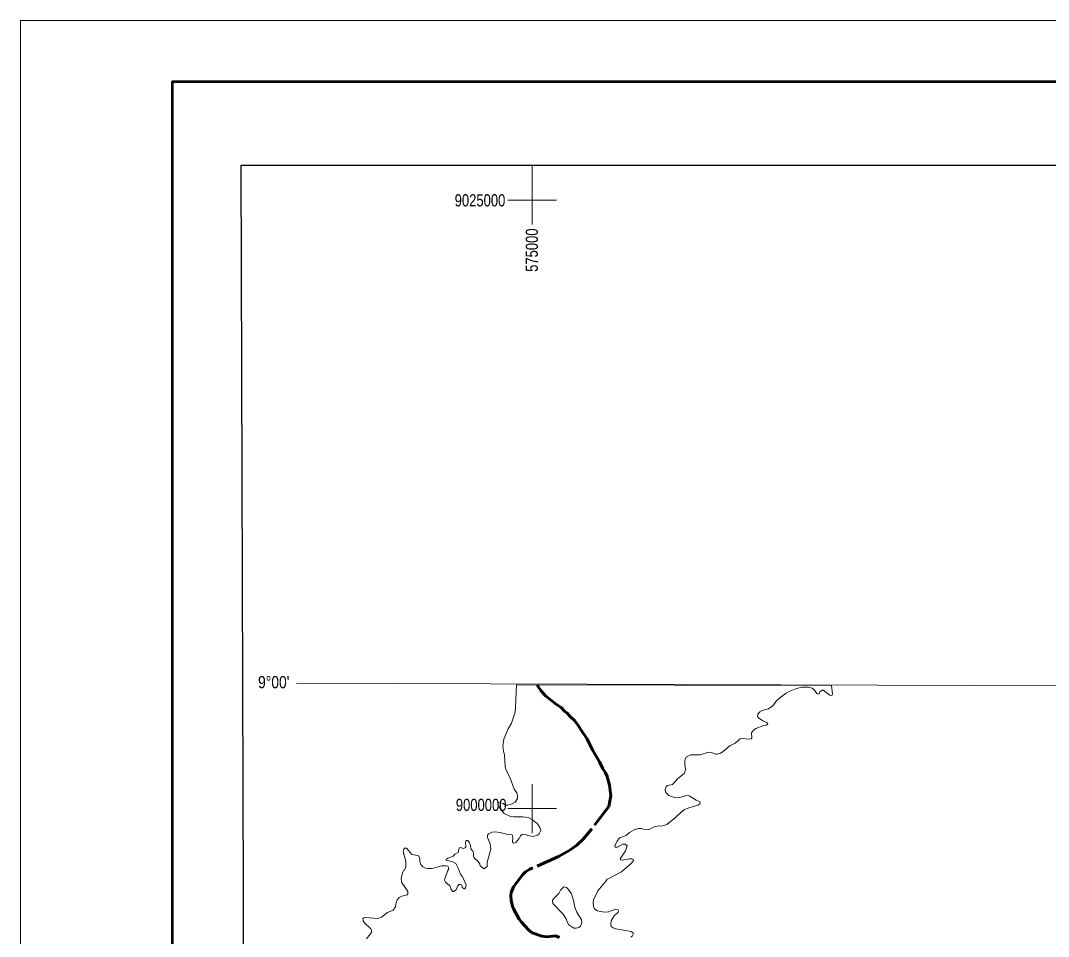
# Model space of a CAD drawing. Extents: x 553962 to 842807, y 8883888 to 9032388.
# Drawn here: x 553962 to 596222, y 8994735 to 9032388 of the extents above; entities that cross this region are included whole.
import ezdxf
from ezdxf.enums import TextEntityAlignment as Align

# ---------------------------------------------------------------- set-up
doc = ezdxf.new("R2010")
doc.units = 0
doc.header["$LTSCALE"] = 160
doc.linetypes.add('LONG_DASH_SHORT_DASH', pattern=[9.9, 6, -1.2, 1.5, -1.2])
for name, color, linetype, lineweight in [('1', 7, 'Continuous', 13), ('2', 7, 'Continuous', 13), ('21', 7, 'Continuous', 25), ('34', 7, 'LONG_DASH_SHORT_DASH', 60)]:
    doc.layers.add(name, color=color, linetype=linetype, lineweight=lineweight)

msp = doc.modelspace()

# ---------------------------------------------------------------- linework, layer by layer
at = {"layer": '1'}
for p, q in [((575000, 9024000), (575000, 9026438.8)), ((574000, 9025000), (576000, 9025000)), ((575000, 8999000), (575000, 9001000)), ((574000, 9000000), (576000, 9000000))]:
    msp.add_line(p, q, dxfattribs=at)
msp.add_lwpolyline([(842807.3, 9032387.8), (842807.3, 8883887.8), (553961.7, 8883887.8), (553961.7, 9032387.8)], close=True, dxfattribs=at)
at = {"layer": '1', "lineweight": 53}
msp.add_lwpolyline([(840307.3, 9029887.8), (840307.3, 8886387.8), (560211.7, 8886387.8), (560211.7, 9029887.8)], close=True, dxfattribs=at)
at = {"layer": '1', "lineweight": 25}
msp.add_lwpolyline([(563033.9, 9026438.8), (793061.1, 9026438.8), (793495.6, 8889836.8), (563468.3, 8889836.8)], close=True, dxfattribs=at)
at = {"layer": '2'}
msp.add_lwpolyline([(565303.2, 9005146.6), (664889.8, 9004806.7), (719872.1, 9004543.9), (791662, 9004102.7)], dxfattribs=at)
at = {"layer": '21', "lineweight": 13}
msp.add_line((587296.7, 9005052), (574348.1, 9005079.3), dxfattribs=at)
for points in [[(574348.1, 9005079.3), (574317.4, 9004163), (574295.7, 9003956), (574144.4, 9003506.6), (574014.7, 9003264.2), (573829.1, 9002845.8), (573792.1, 9002568.4), (573811.5, 9002356.8), (573854.8, 9002205), (573887.2, 9001708), (573923.9, 9001569.9), (574075.2, 9001284.5), (574252.7, 9000793.7), (574360.6, 9000635.8), (574399.5, 9000497.4), (574399.6, 9000400.4), (574293.6, 9000261.8), (574170.4, 9000188.3), (573989.5, 9000125.8), (573897.6, 9000125.8), (573807.4, 9000194.6), (573651.6, 9000255.2), (573610.4, 9000246.4), (573582.4, 9000173.4), (573662.4, 8999991.6), (573850.3, 8999788.5), (574105.5, 8999671.6), (574225.9, 8999652.2), (574616, 8999647.8), (574834.5, 8999622.2), (575013.7, 8999535.3), (575214.5, 8999368.9), (575311.9, 8999208.8), (575350.7, 8999090.1), (575283.8, 8998949.8), (575211.7, 8998895.2), (575030.5, 8998839.4), (574820.5, 8998888.6), (574709.3, 8998932.6), (574600.8, 8998934.5), (574550.9, 8998912.8), (574512, 8998871.7), (574467, 8998760.2), (574328, 8998599.3), (574233.6, 8998567), (574187.8, 8998629.6), (574204.6, 8998800.2), (574169.9, 8998917.3), (573924.2, 8998943.1), (573861.2, 8998973.3), (573495.9, 8999038.2), (573357.6, 8999025.2), (573195.7, 8998954), (573160.9, 8998904.1), (573154.4, 8998796.3), (573264.6, 8998547.5), (573290.5, 8998318.6), (573147.9, 8997786.5), (573147.7, 8997610.4), (573041.5, 8997523.5), (573000.7, 8997531.6), (572856.3, 8997643.8), (572845.2, 8997713), (572780.5, 8997814.4), (572609.7, 8997966), (572588, 8998037.6), (572585.8, 8998184.3), (572553.4, 8998244.8), (572469.1, 8998340), (572464.8, 8998478.1), (572423.8, 8998581.8), (572354.7, 8998677), (572291.7, 8998674.9), (572271.2, 8998655.2), (572257.2, 8998599.6), (572268, 8998409.4), (572236.1, 8998375.1), (572164.3, 8998348.7), (572065.1, 8998398.3), (572002.4, 8998374.6), (571967.6, 8998284), (571974, 8998195.7), (571816.4, 8998119.6), (571747.1, 8998035.2), (571528.9, 8997959.6), (571454.6, 8997898.7), (571466.8, 8997864.9), (571737.3, 8997804.6), (571855.7, 8997734.5), (571967.5, 8997514.1), (572052.2, 8997299.3), (572136.7, 8997188.2), (572285.2, 8996857.2), (572259.3, 8996727.3), (572229.1, 8996686.3), (572195.3, 8996686.2), (572121.1, 8996746.8), (572103.5, 8996844.1), (572051.6, 8996874.3), (571987.6, 8996870.2), (571987.6, 8996870.2)], [(578829.1, 8998253.7), (578829.1, 8998253.7), (578893.5, 8998421.2), (578896, 8998462.9), (578820.3, 8998527.9), (578723.1, 8998528), (578498.5, 8998400.6), (578409.9, 8998402.6), (578394.5, 8998476.1), (578489.6, 8998655.6), (578593.2, 8998782.9), (578859, 8998891.1), (578995.7, 8999003.7), (579185.5, 8999124.5), (579245.2, 8999145.9), (579291.8, 8999144.2), (579351.3, 8999169.6), (579492.4, 8999170), (579561.6, 8999144.2), (579767.2, 8999116.1), (580013.9, 8999239.3), (580201.7, 8999282.4), (580318.7, 8999271.8), (580526.2, 8999343.3), (580889.2, 8999621.9), (581105.3, 8999831.3), (581265.1, 8999950.3), (581472.9, 9000039.1), (581818.5, 9000129.8), (581887.7, 9000186), (581907.3, 9000221.2), (581887.7, 9000272.6), (581740.7, 9000331.1), (581525, 9000480), (581446.9, 9000516.8), (581343.2, 9000525.5), (581066.4, 9000443.4), (580893.5, 9000437), (580608.7, 9000531.7), (580484.7, 9000649.6), (580463.4, 9000778.4), (580500.2, 9000888.6), (580562.8, 9000942.6), (580759.6, 9000984), (580990.8, 9001234.6), (581168, 9001360), (581260.1, 9001451.7), (581298.8, 9001611), (581269.7, 9001811.5), (581267.5, 9001967.7), (581280.6, 9002023.8), (581345.4, 9002123), (581515.4, 9002200.7), (581905.2, 9002198.8), (582242.4, 9002304.6), (582365.5, 9002291.2), (582536.5, 9002231.2), (582601.1, 9002231.2), (582739.9, 9002272.4), (582854.4, 9002335.1), (583124.7, 9002577.1), (583340.8, 9002674.5), (583541.9, 9002858.1), (583651.7, 9002877.5), (583929.3, 9002846), (584004.2, 9002858.1), (584030.8, 9002904.2), (584017.3, 9003104.5), (584099.4, 9003216.9), (584192.4, 9003289.2), (584481.8, 9003391.9), (584629.6, 9003423.7), (584682.7, 9003471.9), (584658.6, 9003520.2), (584473.2, 9003604), (584302.8, 9003722.6), (584259.5, 9003783.3), (584268.2, 9003872.1), (584354.7, 9003962.9), (584458.5, 9004027.7), (584711.2, 9004098.9), (584888.4, 9004222.2), (585025.2, 9004408.7), (585173.7, 9004544.1), (585437.6, 9004740.9), (585593, 9004823), (585860.5, 9004930.9), (586094, 9004976.5), (586360.6, 9004989.5), (586505.2, 9004940), (586587.3, 9004879.5), (586702.2, 9004719.4), (586749.8, 9004689.2), (586792.6, 9004706), (586819.4, 9004784.7), (586914.3, 9004864.1), (586966.1, 9004855.3), (587240.7, 9004654.4), (587315.8, 9004635.1), (587350.6, 9004699.9), (587296.7, 9005052)], [(571987.6, 8996870.2), (571926.5, 8996807.2), (571865.9, 8996647.3), (571765.8, 8996584.6), (571736.3, 8996582.5), (571667.1, 8996658.1), (571606.5, 8996815.9), (571427, 8996963.1), (571394.8, 8997042.6), (571399.2, 8997108.2), (571513.5, 8997414.5), (571561.1, 8997492.8), (571561.1, 8997570.3), (571528.4, 8997620.1), (571442, 8997643.9), (571269.3, 8997639.5), (570879.9, 8997529.3), (570707.2, 8997522.8), (570605.6, 8997535.8), (570495.4, 8997602.8), (570421.8, 8997687.3), (570378.7, 8997803.8), (570376.4, 8997959.5), (570326.5, 8998050.2), (570039.3, 8998110.8), (569862.2, 8998339.7), (569828.8, 8998363.9), (569747.5, 8998367.9), (569719.3, 8998318.1), (569695.6, 8998210), (569803.5, 8997832.4), (569805.7, 8997600.4), (569753.7, 8997466.5), (569708.6, 8997447), (569671.8, 8997384.4), (569607, 8997125.3), (569624.2, 8996969.4), (569883.5, 8996580.5), (569890, 8996489.7), (569862.1, 8996442.2), (569634.2, 8996387.6), (569524.8, 8996331.6), (569444.9, 8996241), (569401.6, 8996135.2), (569377.7, 8995955.6), (569276.2, 8995821.7), (569042.7, 8995719.9), (568806.8, 8995531.7), (568653.5, 8995475.6), (568134.7, 8995512.3), (568072.2, 8995501.6), (568030.8, 8995462.5), (568041.7, 8995378.5), (568108.6, 8995287.8), (568364, 8995043), (568387.6, 8994997.6), (568385.5, 8994911.7), (568342.3, 8994825.1), (568190.7, 8994643.1)], [(579056.6, 8994710.7), (579110.2, 8994751.7), (579148.9, 8994826.5), (579144.5, 8994883.2), (579060.1, 8994943.9), (578441.8, 8995047.7), (578329.4, 8995084.5), (578249.8, 8995140.6), (578236.7, 8995240.2), (578245.4, 8995378.3), (578366.5, 8995580.6), (578530.6, 8995730.7), (578550, 8995787.2), (578517.8, 8995849.4), (578440.2, 8995858.2), (578130.8, 8995748), (577961.2, 8995733), (577680.9, 8995784.9), (577577.2, 8995854.1), (577540.6, 8995897.2), (577519, 8995958), (577506, 8996126), (577520.1, 8996237.3), (577700.6, 8996606.2), (578044.1, 8997021.1), (578079, 8997088.2), (578122.3, 8997097.1), (578675.5, 8997397.4), (579083.3, 8997753.4), (579161.9, 8997851.6), (579155.2, 8997899), (579090.3, 8997927), (578978.2, 8997924.9), (578697.2, 8997866.6), (578621.6, 8997888.2), (578612.9, 8997926.9), (578829.1, 8998253.7)]]:
    msp.add_lwpolyline(points, dxfattribs=at)
msp.add_lwpolyline([(576838, 8995728.5), (577030.4, 8995421.6), (577043.3, 8995335.1), (577023.9, 8995242.1), (576967.8, 8995145.1), (576915.8, 8995106), (576799.1, 8995073.5), (576714.8, 8995068.6), (576498.8, 8995207.4), (576421.1, 8995358), (576401.5, 8995430.7), (576267.3, 8995648.5), (576085.6, 8995830.3), (576000.3, 8995938.5), (575843.7, 8996083.1), (575828.5, 8996208.2), (575867.5, 8996280), (576094.2, 8996506.7), (576156.7, 8996642.5), (576293.1, 8996778.9), (576409.7, 8996749.2), (576479.1, 8996679.7), (576613.1, 8996489.7), (576693.2, 8996212.8), (576749.4, 8995936.1)], close=True, dxfattribs=at)
at = {"layer": '34'}
msp.add_lwpolyline([(575200.8, 9005066), (575352.9, 9004840.4), (575540.7, 9004624.5), (575990.8, 9004276.1), (576191.4, 9004153), (576345, 9003982.4), (576418.6, 9003930.3), (576572.1, 9003761.7), (576736.2, 9003614.8), (576870.3, 9003433.3), (576976.4, 9003251.5), (577248.6, 9002866.9), (577488.7, 9002382.5), (577761.4, 9001910.5), (577888.7, 9001647.5), (578007.4, 9001466.1), (578081, 9001303.7), (578180.5, 9000960), (578223.7, 9000519.2), (578145.6, 9000073.3), (577379.3, 8999071.7), (577093.1, 8998733.4), (576838.2, 8998485), (576539.7, 8998279.4), (576081.4, 8998015.7), (574896.8, 8997496.8), (574728.1, 8997390.9), (574617.9, 8997285), (574345.3, 8996938.9), (574235.1, 8996770.3), (574135.8, 8996545.7), (574116.4, 8996433.3), (574127.2, 8996208.5), (574183.3, 8995983.9), (574230.8, 8995871.5), (574464.4, 8995447.5), (574555.2, 8995326.5), (574842.5, 8995008.9), (575001.4, 8994887.2), (575394, 8994749.3), (575618.8, 8994712.5), (575955.7, 8994764.3), (576124.6, 8994693)], dxfattribs=at)

# ---------------------------------------------------------------- texts
at = {"layer": '1', "width": 0.8}
for s, p in [('9025000', (572850.9, 9024747.7)), ('9000000', (572898.5, 8999894))]:
    msp.add_text(s, height=500, dxfattribs=at).set_placement(p, align=Align.CENTER)
msp.add_text('575000', height=500, rotation=90, dxfattribs=at).set_placement((575230.8, 9022948.6), align=Align.CENTER)
at = {"layer": '2', "width": 0.85}
msp.add_text("9°00'", height=500, dxfattribs=at).set_placement((564370.9, 9004939.3), align=Align.CENTER)

doc.saveas('drawing.dxf')
